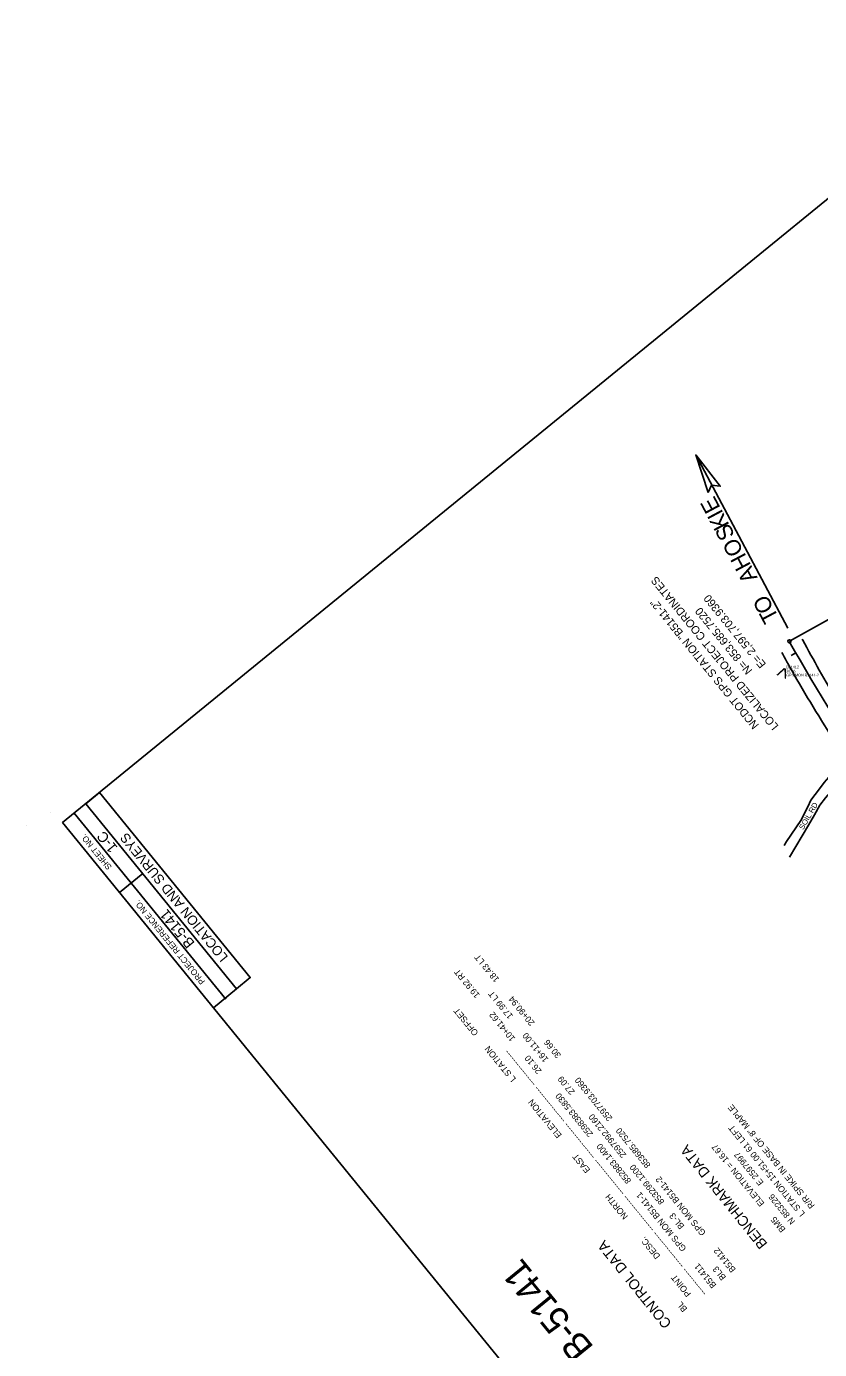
# Model space of a CAD drawing. Extents: x 2596159 to 2598075, y 851667 to 853493.
# Drawn here: x 2596159 to 2596820, y 852390 to 853493 of the extents above; entities that cross this region are included whole.
import ezdxf

# ---------------------------------------------------------------- set-up
doc = ezdxf.new("R2010")
doc.units = 0
for name, color, linetype in [('CTL Sheet Datum Description CELL', 7, 'Continuous'), ('CTL Sheet Text', 7, 'Continuous'), ('CTL Supplemental Horizontal and Vertical Cogo Comment', 7, 'Continuous'), ('CTL Supplemental Horizontal and Vertical Cogo Elevation', 7, 'Continuous'), ('CTL Supplemental Horizontal and Vertical Cogo Number', 7, 'Continuous'), ('Default', 7, 'Continuous'), ('Exist Roads EOP', 7, 'Continuous'), ('Exist Roads Soil', 7, 'Continuous'), ('Exist Roads Soil Text', 7, 'Continuous'), ('Old_Level_1', 7, 'Continuous'), ('Old_Level_18', 7, 'Continuous'), ('Old_Level_2', 7, 'Continuous'), ('Old_Level_40', 7, 'Continuous'), ('Old_Level_44', 7, 'Continuous'), ('Old_Level_50', 7, 'Continuous'), ('Old_Level_52', 7, 'Continuous'), ('Prop Horizontal Alignment', 7, 'Continuous'), ('Prop Horizontal Alignment Station Label', 7, 'Continuous'), ('Prop Horizontal Alignment Tick Small', 7, 'Continuous'), ('Prop Terminator CELL', 7, 'Continuous')]:
    doc.layers.add(name, color=color, linetype=linetype)

msp = doc.modelspace()

# ---------------------------------------------------------------- linework, layer by layer
at = {"layer": 'Default'}
msp.add_line((2596793.4, 852991.4), (2596716.7, 853135.7), dxfattribs=at)
at = {"layer": 'Exist Roads EOP'}
for p, q in [((2596805.9, 852981.4), (2596805.4, 852982.2)), ((2596789.2, 852969.7), (2596788.5, 852971))]:
    msp.add_line(p, q, dxfattribs=at)
for points in [[(2597043.4, 852655.6), (2596986.4, 852724.5), (2596929.8, 852794.5), (2596890.1, 852847.6), (2596852, 852903.2), (2596819.7, 852956.4), (2596805.9, 852981.4)], [(2597027.8, 852643.1), (2596971.2, 852711.2), (2596914.3, 852781.9), (2596874.4, 852834.9), (2596835.8, 852892.1), (2596798.8, 852952.5), (2596789.2, 852969.7)]]:
    msp.add_spline(points, degree=3, dxfattribs=at)
at = {"layer": 'Exist Roads Soil'}
for points in [[(2596835.5, 852892.8), (2596836.1, 852887.3), (2596836.2, 852883.6), (2596835.3, 852879.4), (2596834.2, 852876.4), (2596832.4, 852872.8), (2596830.3, 852870.1), (2596827.6, 852867.2), (2596823.7, 852862.8), (2596820.7, 852858.5), (2596816.4, 852852.7), (2596812.8, 852847.9), (2596810.2, 852842.6), (2596804.2, 852831), (2596792.3, 852813.7), (2596790.4, 852810.2)], [(2596795, 852800.6), (2596810.6, 852827.1), (2596815.7, 852835.9), (2596820.3, 852843.8), (2596824.9, 852849.9), (2596828.6, 852854.2), (2596831.9, 852857.7), (2596834.9, 852860), (2596838.3, 852861.6), (2596844.1, 852862.6), (2596849.7, 852861.7), (2596854.8, 852859.8), (2596858.1, 852858.5)]]:
    msp.add_lwpolyline(points, dxfattribs=at)
at = {"layer": 'Old_Level_1'}
msp.add_line((2596179.2, 852837.4), (2596179.2, 852837.4), dxfattribs=at)
at = {"layer": 'Old_Level_18'}
msp.add_lwpolyline([(2596922.8, 851929.1), (2596189, 852829.3), (2597002.9, 853492.7), (2597950.7, 852330), (2597136.8, 851666.6), (2596922.8, 851929.1)], dxfattribs=at)
at = {"layer": 'Old_Level_40'}
for p, q in [((2596325.2, 852682.2), (2596198.8, 852837.2)), ((2596236.5, 852771.2), (2596255.8, 852787)), ((2596314.8, 852675.1), (2596334.1, 852690.9))]:
    msp.add_line(p, q, dxfattribs=at)
msp.add_lwpolyline([(2596334.1, 852690.9), (2596208.5, 852845.1), (2596219.9, 852854.4), (2596345.5, 852700.2)], close=True, dxfattribs=at)
at = {"layer": 'Old_Level_50'}
msp.add_line((2596158.9, 852826.7), (2596158.9, 852826.7), dxfattribs=at)
at = {"layer": 'Old_Level_52'}
msp.add_line((2596179.2, 852837.4), (2596179.2, 852837.4), dxfattribs=at)
at = {"layer": 'Prop Horizontal Alignment'}
msp.add_arc((2598178.7, 853756.4), 1586.7, 209.2814, 219.7067, dxfattribs=at)
at = {"layer": 'Prop Horizontal Alignment Station Label'}
msp.add_line((2596794.8, 852980.4), (2596909.7, 853044.8), dxfattribs=at)
msp.add_circle((2596794.8, 852980.4), 1.35, dxfattribs=at)
at = {"layer": 'Prop Horizontal Alignment Tick Small'}
msp.add_line((2596800.2, 852970.9), (2596796.3, 852968.7), dxfattribs=at)
at = {"layer": 'Prop Terminator CELL'}
msp.add_lwpolyline([(2596727, 853104.5), (2596716.7, 853135.7), (2596737.1, 853109.6), (2596730, 853110.6)], close=True, dxfattribs=at)

# ---------------------------------------------------------------- texts
at = {"layer": 'CTL Sheet Datum Description CELL'}
for s, p in [('BENCHMARK DATA', (2596776.9, 852478.4)), ('CONTROL DATA', (2596697.1, 852412.1))]:
    msp.add_text(s, height=8.562, rotation=128.798, dxfattribs=at).set_placement(p)
at = {"layer": 'CTL Sheet Text'}
for s, height, p in [('LOCALIZED PROJECT COORDINATES', 6.67, (2596786.1, 852909.8)), ('NCDOT GPS STATION "B5141-2"', 6.67, (2596769.7, 852910.6)), ('E= 2,597,703.9360', 6.67, (2596775.7, 852961.4)), ('N= 853,685.7520', 6.67, (2596764.2, 852956.1)), ('B51412        GPS MON B5141-2      853685.7520     2597703.9360            30.66         20+90.94         18.43 LT', 5.2083, (2596750.4, 852457.1)), ('B51411        GPS MON B5141-1      852883.1400     2598383.5830            26.10         10+41.62         19.92 RT', 5.2083, (2596734.2, 852444)), ('BL3                      BL-3      853299.1200     2597992.2160            27.09         16+11.00         17.99 LT', 5.2083, (2596742.3, 852450.6)), ('    POINT          DESC.           NORTH             EAST          ELEVATION           L STATION       OFFSET', 5.2083, (2596718.1, 852430.8)), ('------------ ---------------- ---------------- ---------------- ---------------- ---------------- ----------------', 5.2083, (2596726.1, 852437.4)), ('R/R SPIKE IN BASE OF 8" MAPLE', 5.208, (2596816.2, 852510.3)), ('L STATION 15+51.00 61 LEFT', 5.208, (2596808.1, 852503.7)), ('BM5       ELEVATION = 16.67', 5.208, (2596791.9, 852490.5)), ('N 853226      E 2597997', 5.208, (2596800, 852497.1)), ('BL', 5.21, (2596710, 852424.2))]:
    msp.add_text(s, height=height, rotation=129.1835, dxfattribs=at).set_placement(p)
at = {"layer": 'CTL Supplemental Horizontal and Vertical Cogo Comment'}
msp.add_text('GPS MON B5141-2', height=2.25, rotation=360, dxfattribs=at).set_placement((2596792.1, 852951.1))
at = {"layer": 'CTL Supplemental Horizontal and Vertical Cogo Elevation'}
msp.add_text('30.66', height=2.25, rotation=360, dxfattribs=at).set_placement((2596792.1, 852954.4))
at = {"layer": 'CTL Supplemental Horizontal and Vertical Cogo Number'}
msp.add_text('B51412', height=2.25, rotation=360, dxfattribs=at).set_placement((2596792.1, 852957.8))
at = {"layer": 'Default'}
for s, p in [('E', (2596737.6, 853091.6)), ('I', (2596740, 853087.1)), ('K', (2596745.1, 853077.4)), ('S', (2596749.7, 853068.9)), ('O', (2596756.9, 853055.4)), ('H', (2596763.1, 853043.7)), ('A', (2596768.5, 853033.4)), ('O', (2596782.1, 853007.9)), ('T', (2596786.3, 853000))]:
    msp.add_text(s, height=13.5, rotation=118.0002, dxfattribs=at).set_placement(p)
at = {"layer": 'Exist Roads Soil Text'}
msp.add_text('SOIL RD', height=4.5, rotation=60.1068, dxfattribs=at).set_placement((2596806.4, 852823))
at = {"layer": 'Old_Level_2'}
msp.add_text('>', height=12, rotation=66.9733, dxfattribs=at).set_placement((2596793, 852947.7))
at = {"layer": 'Old_Level_44'}
for s, height, p in [('SHEET NO.', 5, (2596230.4, 852792.5)), ('1-C', 8.64, (2596235.3, 852808.6)), ('LOCATION AND SURVEYS', 8, (2596327.4, 852717.4)), ('PROJECT REFERENCE NO.', 5, (2596308.1, 852697)), ('B-5141', 8.64, (2596299.6, 852729.1)), ('SURVEY CONTROL SHEET B-5141', 22.5, (2596882.8, 852085))]:
    msp.add_text(s, height=height, rotation=129.1835, dxfattribs=at).set_placement(p)

doc.saveas('drawing.dxf')
